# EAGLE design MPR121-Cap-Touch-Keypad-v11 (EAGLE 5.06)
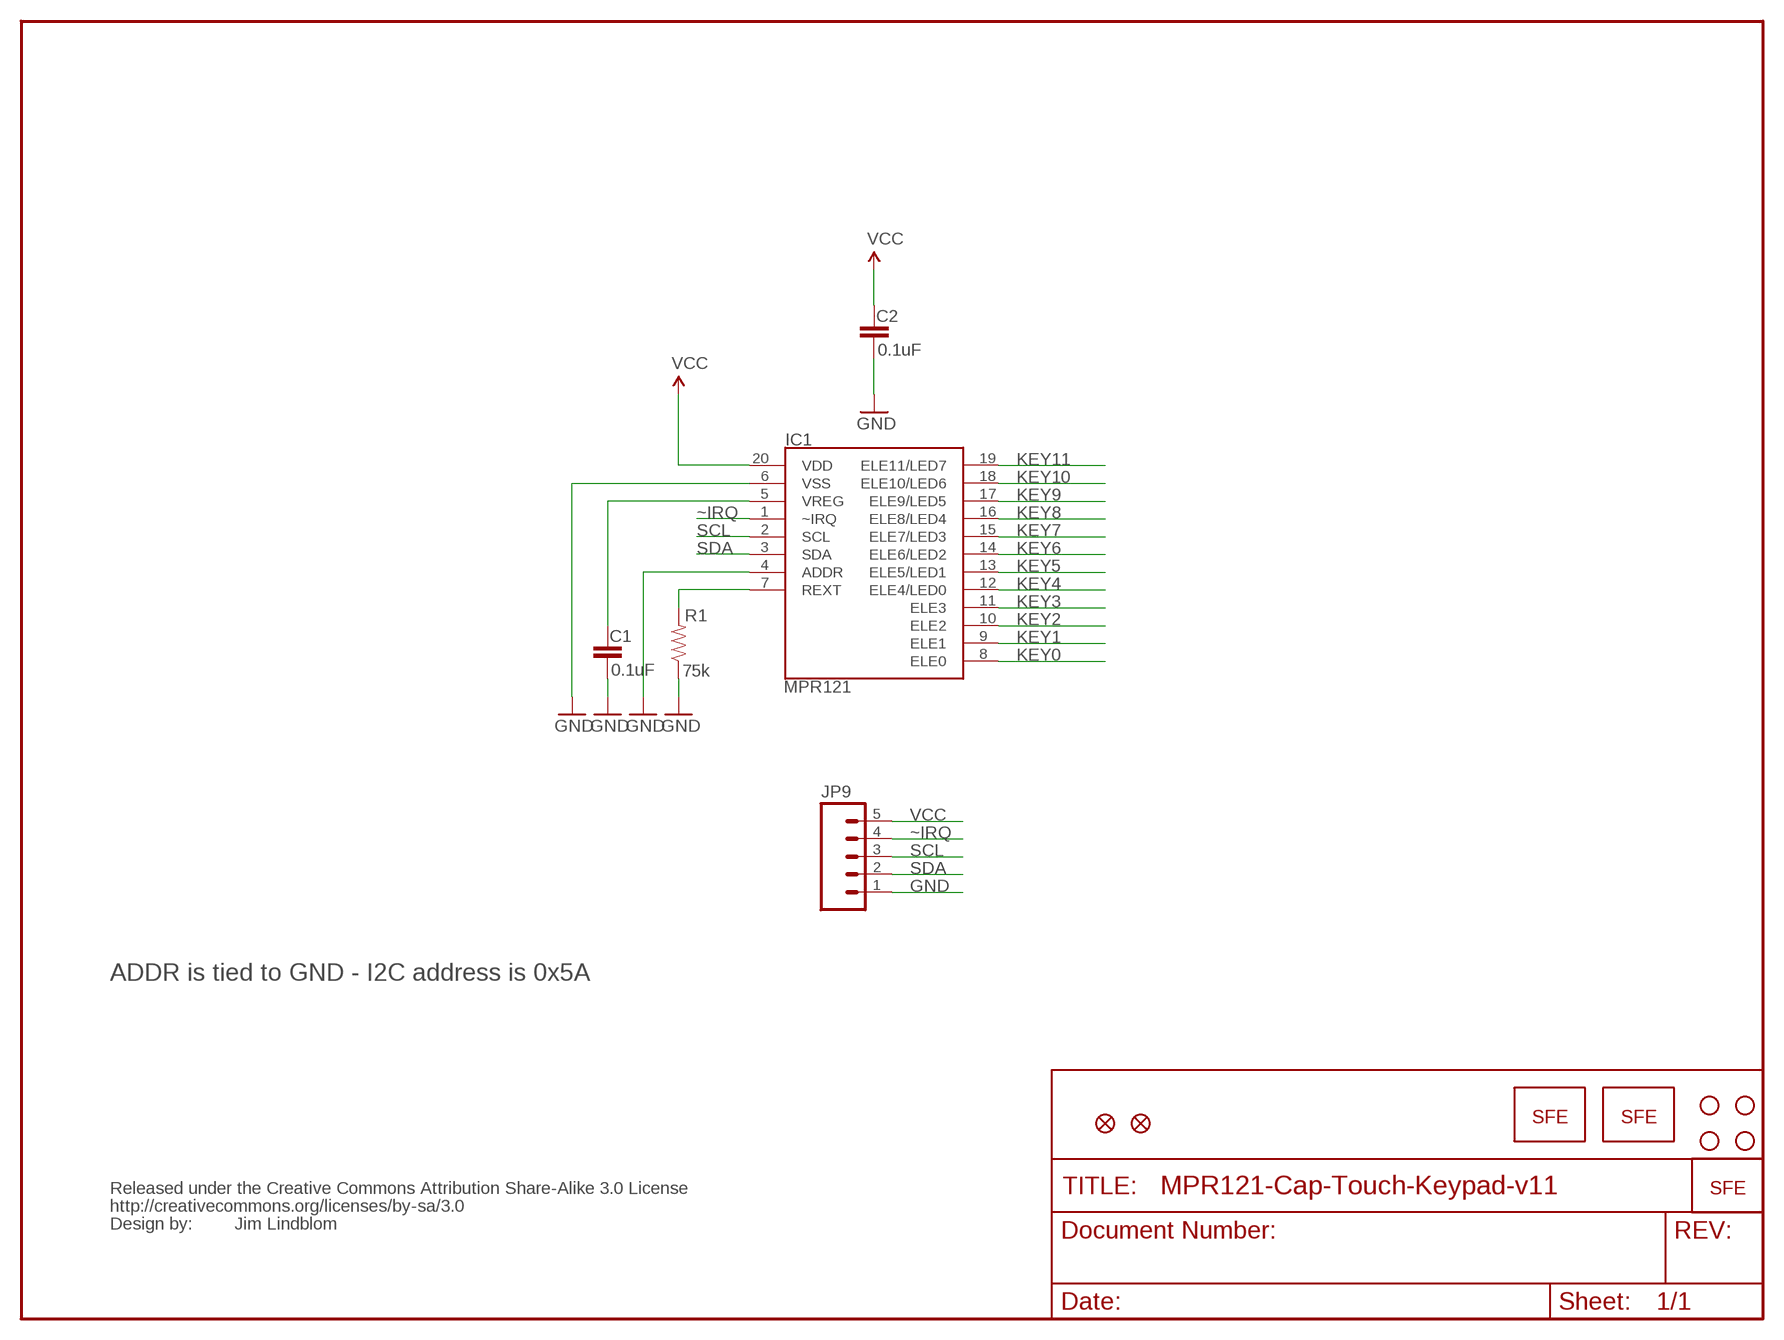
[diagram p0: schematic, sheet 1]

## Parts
C1  0.1uF  CAP0402-CAP  [0402-CAP]
C2  0.1uF  CAP0402-CAP  [0402-CAP]
IC1  MPR121  MPR121QFN20  [QFN-20-0.4MM]
JP1  LOGO-SFENEW  [SFE-NEW-WEBLOGO]
JP2  LOGO-SFESK  [SFE-LOGO-FLAME]
JP3  STAND-OFF  [STAND-OFF]
JP4  STAND-OFF  [STAND-OFF]
JP5  FIDUCIAL1X2  [FIDUCIAL-1X2]
JP6  LOGO-SFESK  [SFE-LOGO-FLAME]
JP7  STAND-OFF  [STAND-OFF]
JP8  STAND-OFF  [STAND-OFF]
JP9  M05PTH  [1X05]
JP10  FIDUCIAL1X2  [FIDUCIAL-1X2]
R1  75k  RESISTOR0402-RES  [0402-RES]
U$1  CREATIVE_COMMONS  [CREATIVE_COMMONS]

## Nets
GND: C1.2 C2.2 IC1.4(ADDR) IC1.6(VSS) JP9.1 R1.1
KEY0: IC1.8(ELE0)
KEY1: IC1.9(ELE1)
KEY2: IC1.10(ELE2)
KEY3: IC1.11(ELE3)
KEY4: IC1.12(ELE4/LED0)
KEY5: IC1.13(ELE5/LED1)
KEY6: IC1.14(ELE6/LED2)
KEY7: IC1.15(ELE7/LED3)
KEY8: IC1.16(ELE8/LED4)
KEY9: IC1.17(ELE9/LED5)
KEY10: IC1.18(ELE10/LED6)
KEY11: IC1.19(ELE11/LED7)
REXT: IC1.7(REXT) R1.2
SCL: IC1.2(SCL) JP9.3
SDA: IC1.3(SDA) JP9.2
VCC: C2.1 IC1.20(VDD) JP9.5
VREG: C1.1 IC1.5(VREG)
~IRQ: IC1.1(~IRQ) JP9.4

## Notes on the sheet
- ADDR is tied to GND - I2C address is 0x5A
- Jim Lindblom

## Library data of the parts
C1 C2 = SparkFun:CAP: Capacitor
IC1 = SparkFun:MPR121: MPR121 Capacitive Touch Sensor Controller
JP1 JP2 JP6 = SparkFun:LOGO-SFE: Spark Fun Electronics PCB Logo
JP3 JP4 JP7 JP8 = SparkFun:STAND-OFF: Stand Off
JP5 JP10 = SparkFun:FIDUCIAL: Fiducial Alignment Points
JP9 = SparkFun:M05: Header 5 Standard 5-pin 0.1" header. Use with straight break away headers (SKU : PRT-00116), right angle break away headers (PRT-00553), swiss pins (PRT-00743), machine pins (PRT-00117), and female headers (PRT-00115). Molex polarized connector foot print use with SKU : PRT-08230 with associated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
R1 = SparkFun:RESISTOR: Resistor
U$1 = SparkFun:CREATIVE_COMMONS

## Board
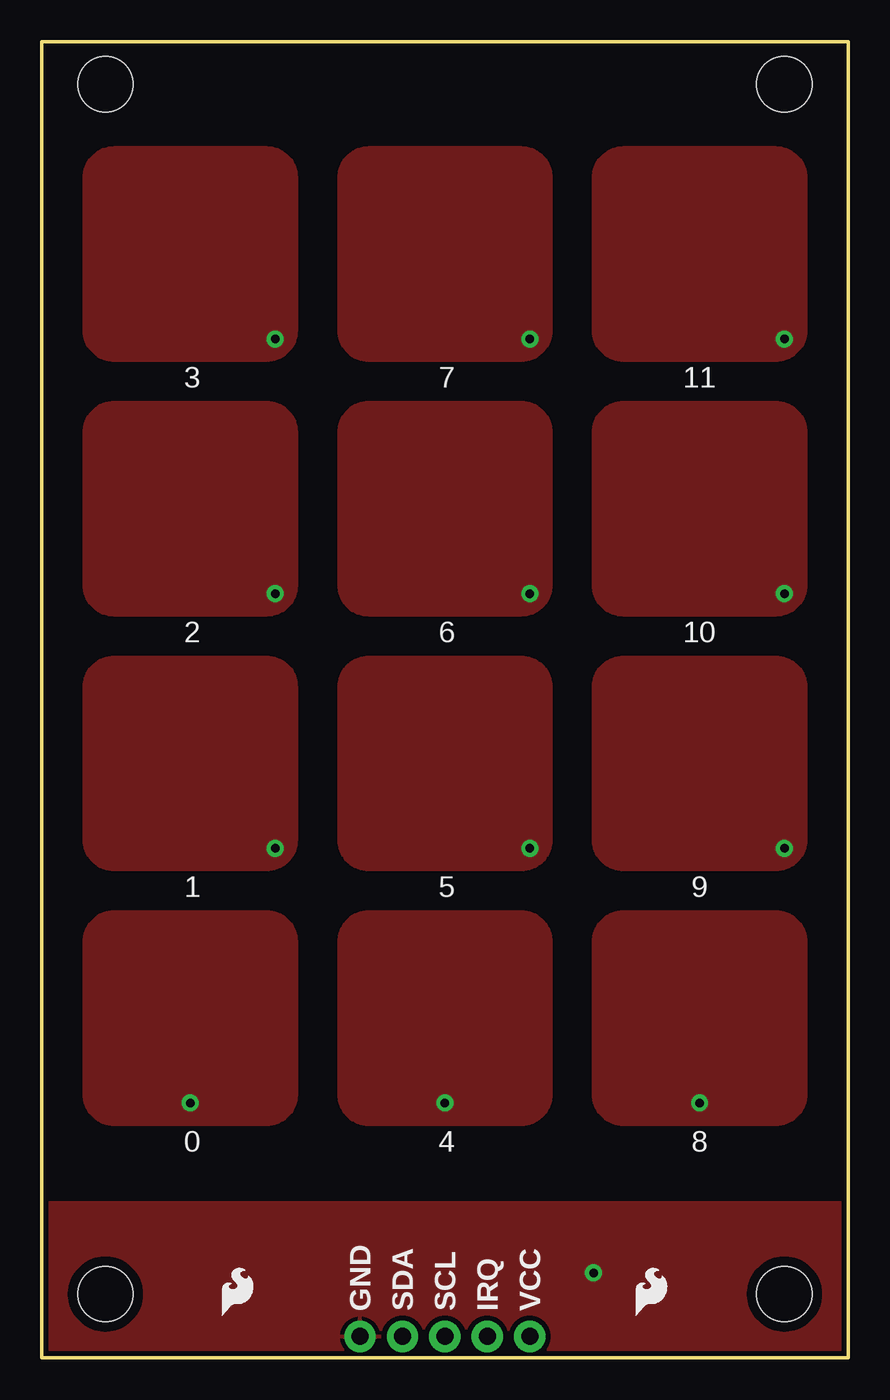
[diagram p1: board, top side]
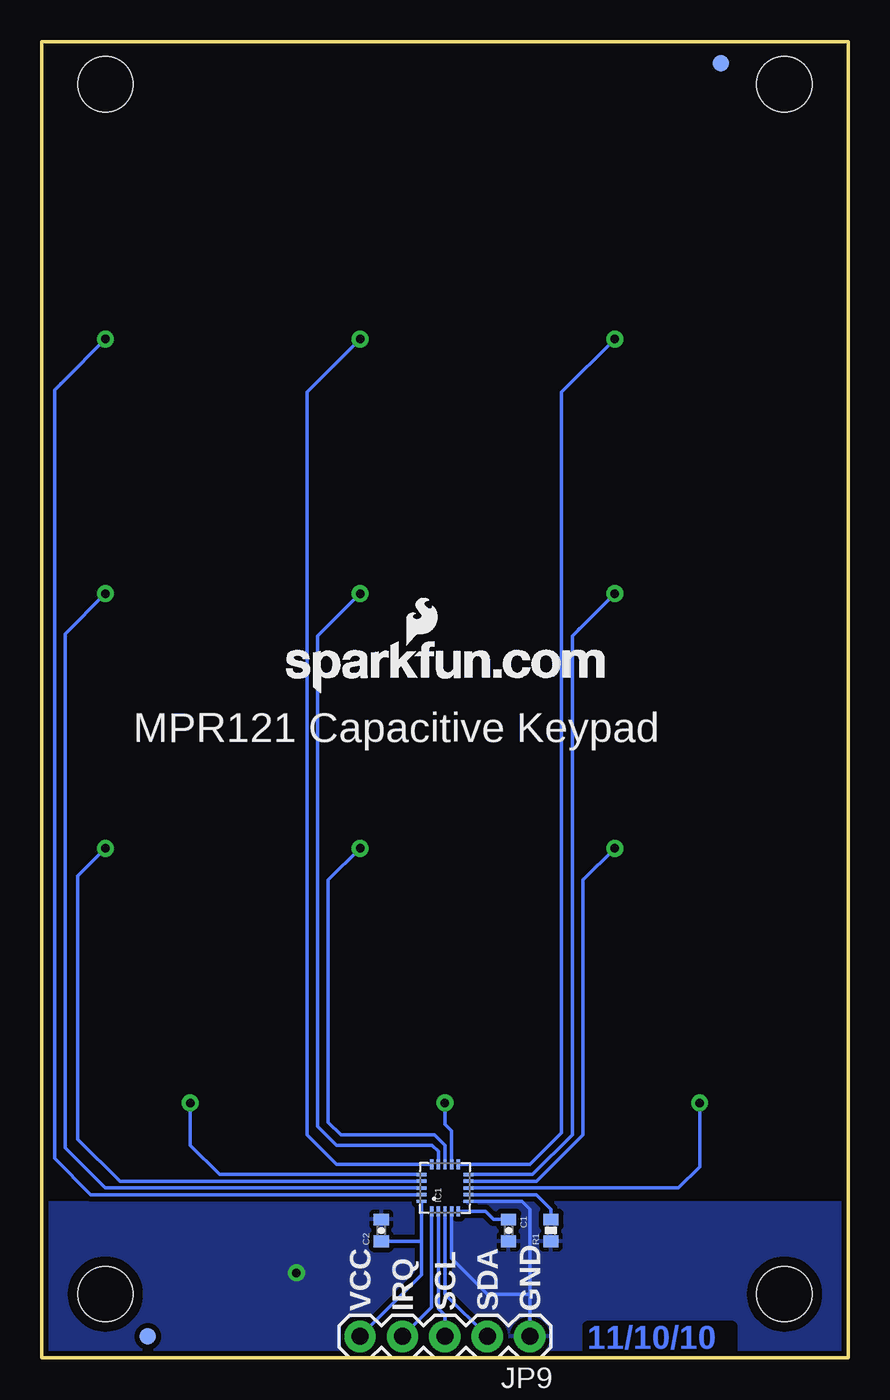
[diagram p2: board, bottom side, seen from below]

Size 48.26 x 78.74 mm. Coordinates in mm from the lower left corner, seen from the top.
Outline: 48.26,0 0,0 0,78.74 48.26,78.74 48.26,0
Copper layers (1*16): Top 0.035mm / dielectric 1.5mm / Bottom 0.035mm
Design rules "SparkFun": minimum track width 8mil, minimum drill 20mil, track to track 8mil, track to pad 8mil, pad to pad 8mil, via to via 8mil, smd to smd 8mil, copper to edge 8mil, drill to drill 8mil, minimum pad ring 12mil, minimum via ring 10mil, stop-mask expansion 4mil, vias tented up to drill 20mil, thermal gap 10mil

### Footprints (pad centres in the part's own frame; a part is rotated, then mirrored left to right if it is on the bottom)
0402-CAP = smd 0.7 x 0.9: 1 -0.65,0; 2 0.65,0
QFN-20-0.4MM = smd 0.6 x 0.2: 1 -1.4,0.8; 2 -1.4,0.4; 3 -1.4,0; 4 -1.4,-0.4; 5 -1.4,-0.8; 11 1.4,-0.8; 12 1.4,-0.4; 13 1.4,0; 14 1.4,0.4; 15 1.4,0.8 | smd 0.2 x 0.6: 6 -0.8,-1.4; 7 -0.4,-1.4; 8 0,-1.4; 9 0.4,-1.4; 10 0.8,-1.4; 16 0.8,1.4; 17 0.4,1.4; 18 0,1.4; 19 -0.4,1.4; 20 -0.8,1.4
STAND-OFF = hole 3.302: 0,0
FIDUCIAL-1X2 = smd 1 x 1: 1 0,0
1X05 = drill 1.016 pad 1.88 round: 1 0,0; 2 2.54,0; 3 5.08,0; 4 7.62,0; 5 10.16,0
0402-RES = smd 0.7 x 0.9: 1 -0.65,0; 2 0.65,0

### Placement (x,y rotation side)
C1  20.32,7.62 270 bottom
C2  27.94,7.62 90 bottom
IC1  24.13,10.16 90 bottom
JP1  33.66,39.75 0 bottom
JP2  10.79,2.54 0 top
JP3  44.45,3.81 0 bottom
JP4  3.81,3.81 0 bottom
JP5  7.62,77.47 0 bottom
JP6  35.56,2.54 0 top
JP7  44.45,76.2 0 bottom
JP8  3.81,76.2 0 bottom
JP9  19.05,1.27 180 bottom
JP10  41.91,1.27 0 bottom
R1  17.78,7.62 90 bottom
U$1  48.26,-2.54 0 bottom

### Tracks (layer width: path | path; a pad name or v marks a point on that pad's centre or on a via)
GND  (via drill 0.51)
  Bottom 0.203: IC1.6 19.52,9.36 19.05,8.89 19.05,3.81 | IC1.4 23.73,5.95 21.59,3.81 19.05,3.81 | JP9.1 19.05,3.81
  other vias: 33.02,5.08
  pour Top (isolate 0.305): 48.26,0 48.13,9.27 0,9.27 0,0
  pour Bottom (isolate 0.305): 48.26,0 48.26,9.27 0,9.27 0,0
KEY0  (via drill 0.51)
  Bottom 0.203: IC1.8 10.16,10.16 8.89,11.43 v8.89,15.24
  pour Top (isolate 0.305): 13.44,13.97 arc90 15.24,15.77 15.24,24.87 arc90 13.44,26.67 4.34,26.67 arc90 2.54,24.87 2.54,15.77 arc90 4.34,13.97
KEY1  (via drill 0.51)
  Bottom 0.203: IC1.9 18.65,10.56 15.88,13.34 15.88,28.57 v13.97,30.48
  pour Top (isolate 0.305): 15.24,40.11 arc90 13.44,41.91 4.34,41.91 arc90 2.54,40.11 2.54,31.01 arc90 4.34,29.21 13.44,29.21 arc90 15.24,31.01
KEY2  (via drill 0.51)
  Bottom 0.203: IC1.10 18.89,10.96 16.51,13.34 16.51,43.18 15.88,43.81 | 15.88,43.81 16.13,43.56 | 15.88,43.81 v13.97,45.72
  pour Top (isolate 0.305): 15.24,55.35 arc90 13.44,57.15 4.34,57.15 arc90 2.54,55.35 2.54,46.25 arc90 4.34,44.45 13.44,44.45 arc90 15.24,46.25
KEY3  (via drill 0.51)
  Bottom 0.203: IC1.11 19.05,11.56 17.14,13.46 17.14,57.78 v13.97,60.96
  pour Top (isolate 0.305): 15.24,70.59 arc90 13.44,72.39 4.34,72.39 arc90 2.54,70.59 2.54,61.49 arc90 4.34,59.69 13.44,59.69 arc90 15.24,61.49
KEY4  (via drill 0.51)
  Bottom 0.203: IC1.12 23.73,13.57 24.13,13.97 v24.13,15.24
  pour Top (isolate 0.305): 28.68,13.97 arc90 30.48,15.77 30.48,24.87 arc90 28.68,26.67 19.58,26.67 arc90 17.78,24.87 17.78,15.77 arc90 19.58,13.97
KEY5  (via drill 0.51)
  Bottom 0.203: IC1.13 24.13,12.7 24.77,13.34 30.35,13.34 31.11,14.1 31.11,28.57 v29.21,30.48
  pour Top (isolate 0.305): 30.48,40.11 arc90 28.68,41.91 19.58,41.91 arc90 17.78,40.11 17.78,31.01 arc90 19.58,29.21 28.68,29.21 arc90 30.48,31.01
KEY6  (via drill 0.51)
  Bottom 0.203: IC1.14 24.53,12.34 24.89,12.7 30.61,12.7 31.75,13.84 31.75,43.18 v29.21,45.72
  pour Top (isolate 0.305): 30.48,55.35 arc90 28.68,57.15 19.58,57.15 arc90 17.78,55.35 17.78,46.25 arc90 19.58,44.45 28.68,44.45 arc90 30.48,46.25
KEY7  (via drill 0.51)
  Bottom 0.203: IC1.15 30.61,11.56 32.38,13.34 32.38,57.78 v29.21,60.96
  pour Top (isolate 0.305): 30.48,70.59 arc90 28.68,72.39 19.58,72.39 arc90 17.78,70.59 17.78,61.49 arc90 19.58,59.69 28.68,59.69 arc90 30.48,61.49
KEY8  (via drill 0.51)
  Bottom 0.203: IC1.16 37.63,10.96 39.37,12.7 v39.37,15.24
  pour Top (isolate 0.305): 45.72,24.87 arc90 43.92,26.67 34.82,26.67 arc90 33.02,24.87 33.02,15.77 arc90 34.82,13.97 43.92,13.97 arc90 45.72,15.77
KEY9  (via drill 0.51)
  Bottom 0.203: IC1.17 43.58,10.56 46.1,13.08 46.1,28.83 v44.45,30.48
  pour Top (isolate 0.305): 45.72,40.11 arc90 43.92,41.91 34.82,41.91 arc90 33.02,40.11 33.02,31.01 arc90 34.82,29.21 43.92,29.21 arc90 45.72,31.01
KEY10  (via drill 0.51)
  Bottom 0.203: v44.45,45.72 46.86,43.31 46.86,12.57 44.45,10.16 IC1.18
  pour Top (isolate 0.305): 33.02,46.25 arc90 34.82,44.45 43.92,44.45 arc90 45.72,46.25 45.72,55.35 arc90 43.92,57.15 34.82,57.15 arc90 33.02,55.35
KEY11  (via drill 0.51)
  Bottom 0.203: 46.99,58.42 47.12,58.29 | 46.99,58.42 v44.45,60.96 | 46.99,58.42 47.5,57.91 47.5,11.94 45.32,9.76 IC1.19
  pour Top (isolate 0.305): 34.82,72.39 arc90 33.02,70.59 33.02,61.49 arc90 34.82,59.69 43.92,59.69 arc90 45.72,61.49 45.72,70.59 arc90 43.92,72.39
REXT
  Bottom 0.203: IC1.7 18.65,9.76 17.78,8.89 R1.2
SCL
  Bottom 0.203: IC1.2 24.53,2.94 24.13,2.54 JP9.3
SDA
  Bottom 0.203: IC1.3 24.13,3.81 JP9.2
VCC
  Bottom 0.203: 25.53,6.99 25.53,4.95 JP9.5 | 25.53,6.99 IC1.20 | C2.1 25.55,6.97 25.53,6.99
VREG
  Bottom 0.203: IC1.5 21.72,8.76 21.23,8.27 C1.1
~IRQ
  Bottom 0.203: IC1.1 24.93,3.01 JP9.4

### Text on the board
Bottom: 11/10/10
tPlace: 3 | 7 | 11 | 2 | 6 | 10 | 1 | 5 | 9 | 0 | 4 | 8 | GND | SDA | SCL | IRQ | VCC
bPlace: MPR121 Capacitive Keypad | GND | SDA | SCL | IRQ | VCC
Measures: All Dimensions in mil | 3100 | 3000 | 1150 | 1050 | 550 | 400 | 150 | 50 | 0 | 0 | 0 | 0 | 0 | 100 | 150 | 600 | 700 | 750 | 850 | 950 | 1050 | 1150 | 1750 | 1900
Reference: vcc | irq | scl | sda | gnd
